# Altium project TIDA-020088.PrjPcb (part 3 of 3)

## Sheet TIDA-020088_SPDIF and Interface.SchDoc
size 431 x 279 mm; Date: Not shown in title block; ApprovedBy: Not shown in title block; CheckedBy: Not shown in title block; Author: Not shown in title block; CompanyName: Not shown in title block; Engineer: Not shown in title block; Organization: Not shown in title block; Address1: Not shown in title block; Address2: Not shown in title block; Address3: Not shown in title block; Address4: Not shown in title block; DocumentNumber: 2; Revision: Use project parameter SCH_Rev; SheetNumber: 6; SheetTotal: 7; PageSetup: Record=PageOptions¦CenterHorizontal=True¦CenterVertical=True¦PrintScale=1.00¦XCorrection=1.00¦YCorrection=1.00¦PrintKind=0¦BorderSize=5000000¦LeftOffset=0¦BottomOffset=0¦Orientation=2¦PaperLength=1000¦PaperWidth=1000¦Scale=100¦PaperSource=15¦PrintQuality=600¦MediaType=1¦DitherType=10¦PaperKind=Letter¦PrintScaleMode=1
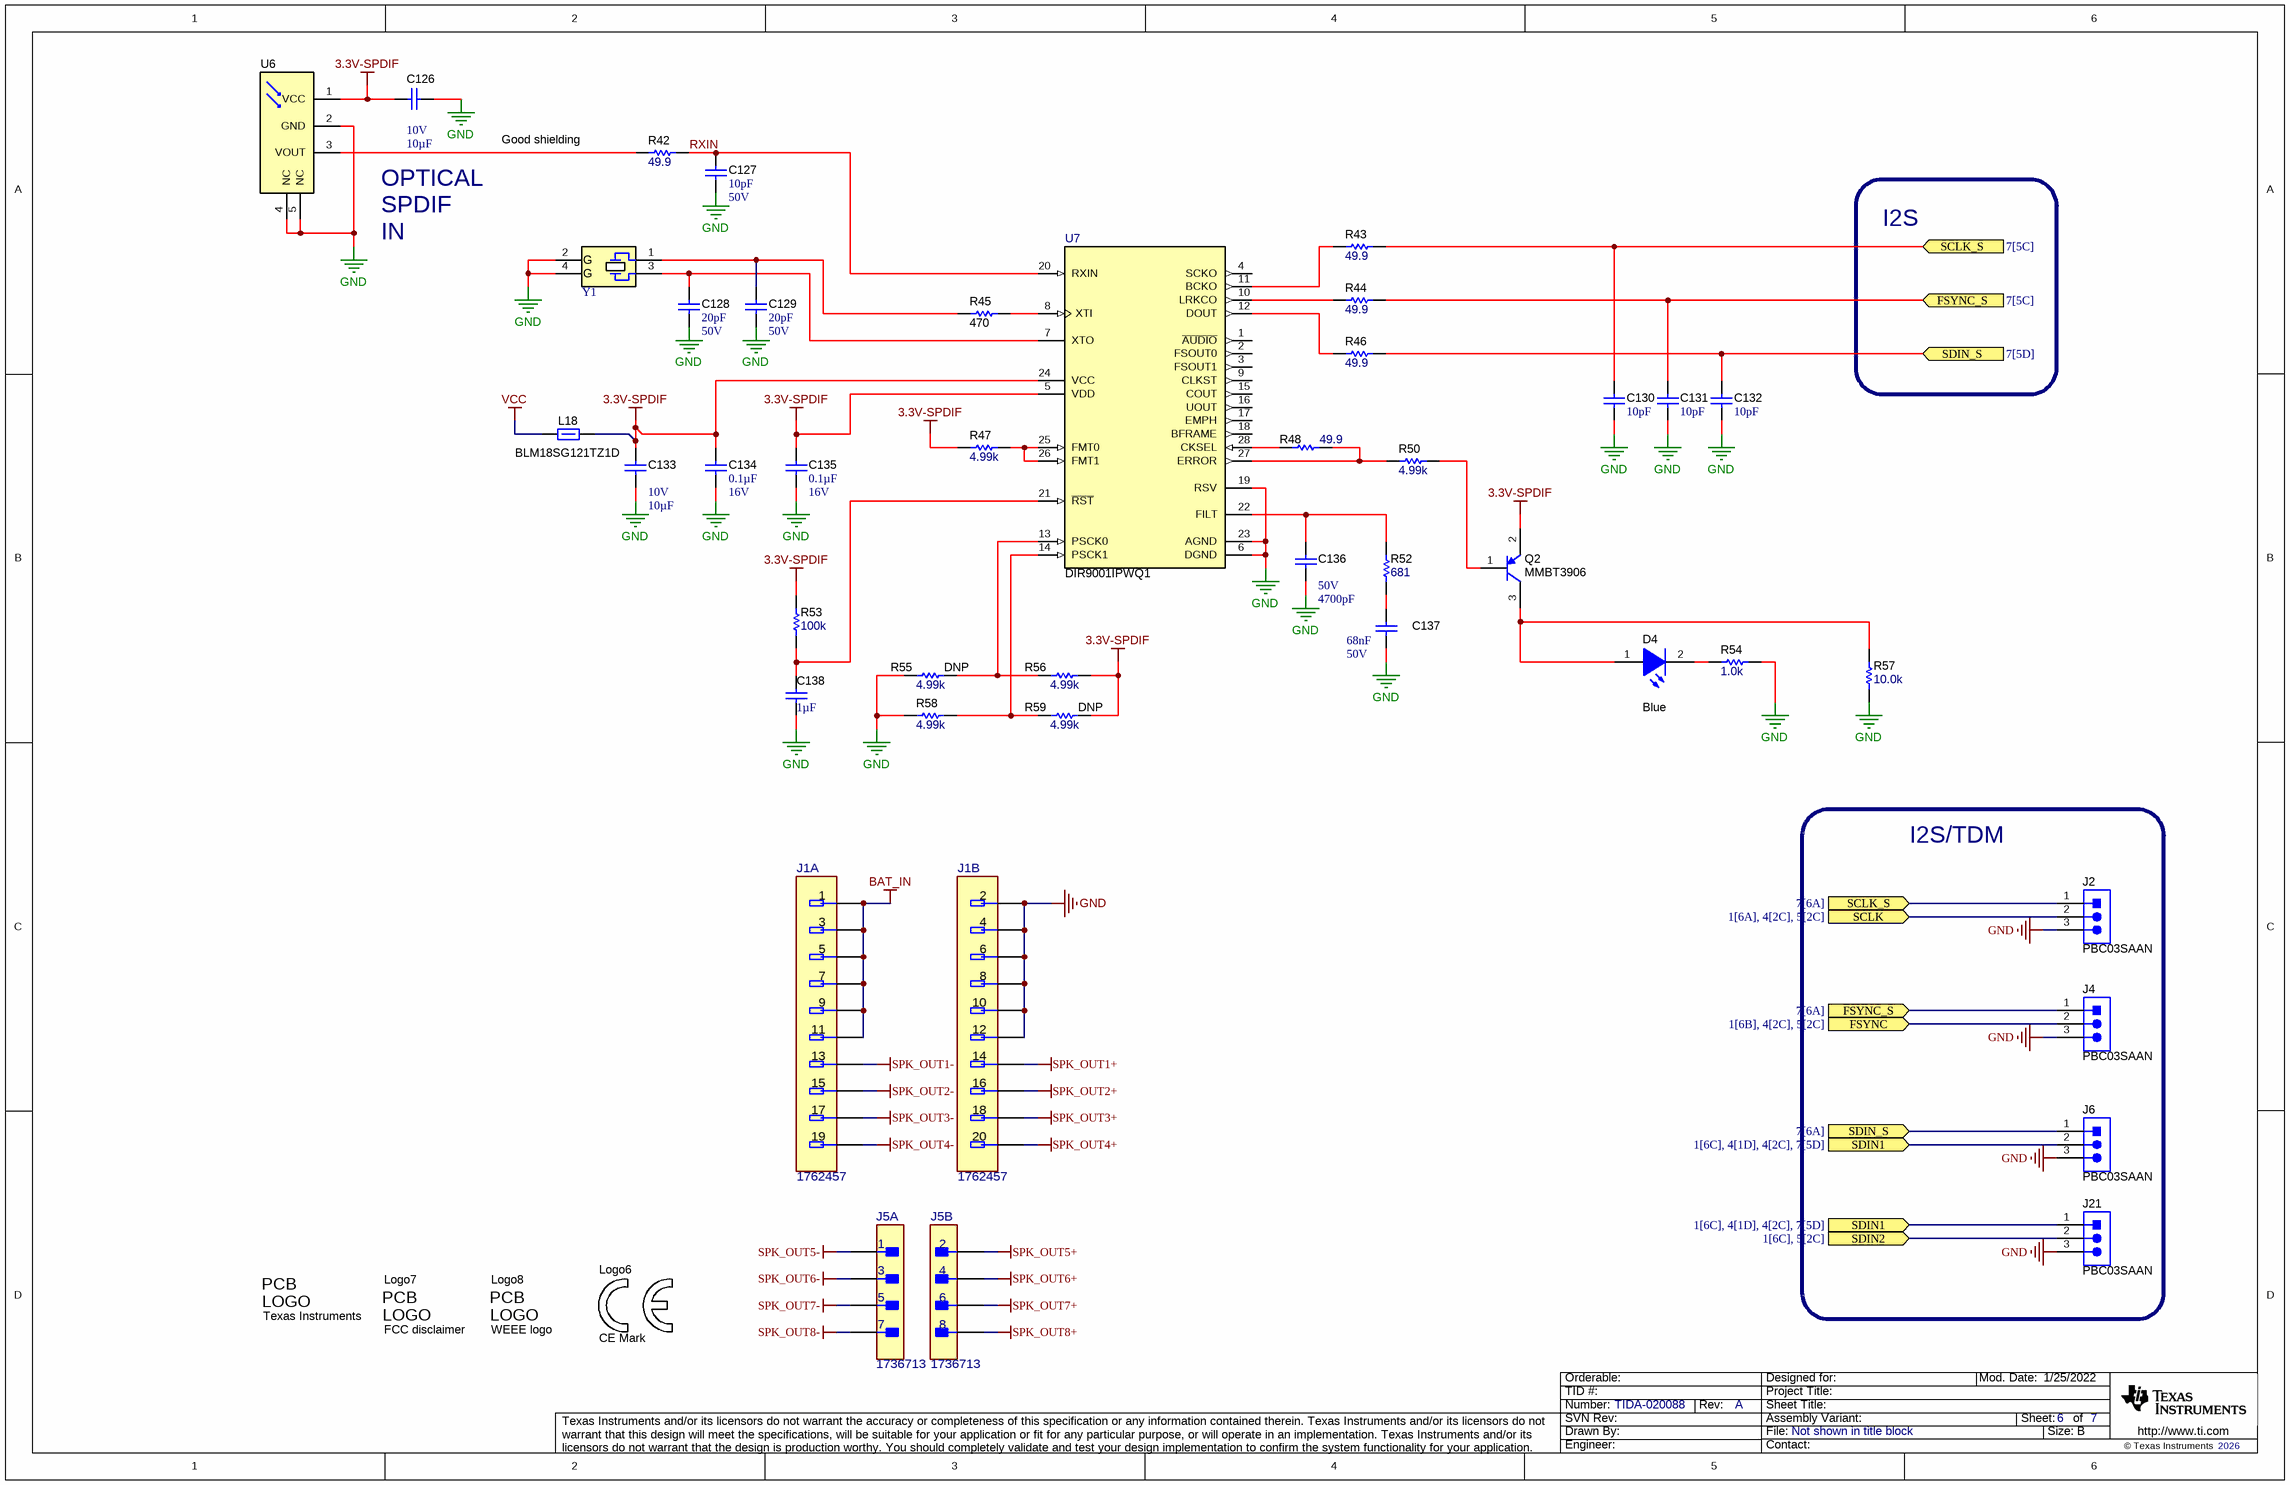
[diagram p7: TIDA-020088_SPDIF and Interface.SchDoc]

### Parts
C126  VDC_V: 10V  ValueDisplayed: 10µF  [0805_HV]  (hidden comment: C0805C106J8RACAUTO)
C127  ValueDisplayed: 10pF  VDC_V: 50V  [0402]  (hidden comment: GCM1555C1H100JA16D)
C128  ValueDisplayed: 20pF  VDC_V: 50V  [0402]  (hidden comment: GCQ1555C1H200JB01D)
C129  ValueDisplayed: 20pF  VDC_V: 50V  [0402]  (hidden comment: GCQ1555C1H200JB01D)
C130  ValueDisplayed: 10pF  [0402]  (hidden comment: GCM1555C1H100JA16D)
C131  ValueDisplayed: 10pF  [0402]  (hidden comment: GCM1555C1H100JA16D)
C132  ValueDisplayed: 10pF  [0402]  (hidden comment: GCM1555C1H100JA16D)
C133  VDC_V: 10V  ValueDisplayed: 10µF  [0805_HV]  (hidden comment: C0805C106J8RACAUTO)
C134  ValueDisplayed: 0.1µF  VDC_V: 16V  [0402]  (hidden comment: GCM155R71C104JA55D)
C135  ValueDisplayed: 0.1µF  VDC_V: 16V  [0402]  (hidden comment: GCM155R71C104JA55D)
C136  VDC_V: 50V  ValueDisplayed: 4700pF  [0402]  (hidden comment: GCM155R71H472KA37D)
C137  Cap_F: 68nF  VDC_V: 50V  [0603]  (hidden comment: CGA3E2X7R1H683K080AA)
C138  Cap_F: 1µF  [0603]  (hidden comment: GCM188R71E105KA64D)
D4  value Blue  [LED_SMLP12_BLUE]  (hidden comment: CMP-0002838-1)
J1  1762457  [FP-1762457_HDR20-MFG]  (parts A,B of 2)
J2  PBC03SAAN  [PBC03SAAN]
J4  PBC03SAAN  [PBC03SAAN]
J5  1736713  [FP-1736713_HDR8-MFG]  (parts A,B of 2)
J6  PBC03SAAN  [PBC03SAAN]
J21  PBC03SAAN  [PBC03SAAN]
L18  BLM18SG121TZ1D  [0603]
Logo5  Texas Instruments  [TI_Stacked_Overlay_Small]  (no BOM)
Logo6  CE Mark  [CE_Mark_5mm]  (no BOM)
Logo7  FCC disclaimer  [FCC_disclaimer_stacked]  (no BOM)
Logo8  WEEE logo  [WEEE_Minimum]  (no BOM)
Q2  MMBT3906  [SOT-23]
R42  ValueDisplayed: 49.9  [0402L]  (hidden comment: CMP-0026404-2)
R43  ValueDisplayed: 49.9  [0402L]  (hidden comment: CMP-0026404-2)
R44  ValueDisplayed: 49.9  [0402L]  (hidden comment: CMP-0026404-2)
R45  ValueDisplayed: 470  [0402L]  (hidden comment: CRCW0402470RJNED)
R46  ValueDisplayed: 49.9  [0402L]  (hidden comment: CMP-0026404-2)
R47  ValueDisplayed: 4.99k  [0402L]  (hidden comment: CMP-0026414-2)
R48  ValueDisplayed: 49.9  [0402L]  (hidden comment: CMP-0026404-2)
R50  ValueDisplayed: 4.99k  [0402L]  (hidden comment: CMP-0026414-2)
R52  ValueDisplayed: 681  [0402L]  (hidden comment: CMP-0026505-2)
R53  ValueDisplayed: 100k  [0402L]  (hidden comment: CMP-0025950-3)
R54  ValueDisplayed: 1.0k  [0402L]  (hidden comment: CRCW04021K00JNED)
R55  DNP  ValueDisplayed: 4.99k  [0402L]
R56  ValueDisplayed: 4.99k  [0402L]  (hidden comment: CMP-0026414-2)
R57  ValueDisplayed: 10.0k  [0402L]  (hidden comment: CMP-0025958-3)
R58  ValueDisplayed: 4.99k  [0402L]  (hidden comment: CMP-0026414-2)
R59  DNP  ValueDisplayed: 4.99k  [0402L]
U6  CMP-0004896-1  [PLR135_T10]  (value not drawn)
U7  PartNumber: DIR9001IPWQ1  [PW0028A_N]  (hidden comment: TI-DIR9001-Q1-TSSOP_PW-28)
Y1  ABM10-24.576MHZ-E20-T  [XTAL_ABM10]  (value not drawn)

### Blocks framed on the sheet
I2S/TDM: J2 J4 J6 J21

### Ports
FSYNC (in, see 1[6B], 4[2C], 5[2C]), FSYNC_S (in, see 7[5C]), FSYNC_S (in, see 7[6A]), SCLK (in, see 1[6A], 4[2C], 5[2C]), SCLK_S (in, see 7[5C]), SCLK_S (in, see 7[6A]), SDIN1 (in, see 1[6C], 4[1D], 4[2C], 7[5D]), SDIN2 (in, see 1[6C], 5[2C]), SDIN_S (in, see 7[5D]), SDIN_S (in, see 7[6A])

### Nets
3.3V-SPDIF: C126.1 C133.1 C134.2 C135.2 L18.1 Q2.2(E) R47.2 R53.2 R56.1 R59.1 U6.1(VCC) U7.5(VDD) U7.24(VCC)
BAT_IN: J1.1 J1.3 J1.5 J1.7 J1.9 J1.11
GND: C126.2 C127.2 C128.2 C129.2 C130.2 C131.2 C132.2 C133.2 C134.1 C135.1 C136.2 C137.2 C138.2 J1.2 J1.4 J1.6 J1.8 J1.10 J1.12 J2.3 J4.3 J6.3 J21.3 R54.2 R55.2 R57.1 R58.2 U6.2(GND) U6.4(NC) U6.5(NC) U7.6(DGND) U7.19(RSV) U7.23(AGND) Y1.2(GND) Y1.4(GND)
SPK_OUT1+: J1.14
SPK_OUT1-: J1.13
SPK_OUT2+: J1.16
SPK_OUT2-: J1.15
SPK_OUT3+: J1.18
SPK_OUT3-: J1.17
SPK_OUT4+: J1.20
SPK_OUT4-: J1.19
SPK_OUT5+: J5.2
SPK_OUT5-: J5.1
SPK_OUT6+: J5.4
SPK_OUT6-: J5.3
SPK_OUT7+: J5.6
SPK_OUT7-: J5.5
SPK_OUT8+: J5.8
SPK_OUT8-: J5.7
VCC: L18.2
RXIN: C127.1 R42.2 U7.20(RXIN)
NetC128_1: C128.1 U7.7(XTO) Y1.3
NetC129_1: C129.1 R45.1 Y1.1
NetC130_1: C130.1 J2.1 R43.2 ; port SCLK_S
NetC131_1: C131.1 J4.1 R44.2 ; port FSYNC_S
NetC132_1: C132.1 J6.1 R46.2 ; port SDIN_S
NetC136_1: C136.1 R52.2 U7.22(FILT)
NetC137_1: C137.1 R52.1
NetC138_1: C138.1 R53.1 U7.21(~{RST})
NetD4_1: D4.1(A) Q2.3(C) R57.2
NetD4_2: D4.2(K) R54.1
NetJ2_2: J2.2 ; port SCLK
NetJ4_2: J4.2 ; port FSYNC
NetJ6_2: J6.2 J21.1 ; port SDIN1
NetJ19_2: J21.2 ; port SDIN2
NetQ2_1: Q2.1(B) R50.1
NetR42_1: R42.1 U6.3(VOUT)
NetR43_1: R43.1 U7.11(BCKO)
NetR44_1: R44.1 U7.10(LRKCO)
NetR45_2: R45.2 U7.8(XTI)
NetR46_1: R46.1 U7.12(DOUT)
NetR47_1: R47.1 U7.25(FMT0) U7.26(FMT1)
NetR48_1: R48.1 U7.28(CKSEL)
NetR48_2: R48.2 R50.2 U7.27(ERROR)
NetR55_1: R55.1 R56.2 U7.13(PSCK0)
NetR58_1: R58.1 R59.2 U7.14(PSCK1)

Not connected (* = marked no-connect by the designer): U7 1(~{AUDIO}) 2(FSOUT0) 3(FSOUT1) 4(SCKO) 9(CLKST) 15(COUT) 16(UOUT) 17(EMPH) 18(BFRAME)

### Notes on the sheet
- Good shielding
- OPTICAL
- SPDIF
- I2S
- IN

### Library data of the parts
C126 C133 = CMP-0081061-1: CAP, CERM, 10 µF, 10 V,+/- 5%, X7R, AEC-Q200 Grade 1, 0805; Manufacturer: Kemet; TaMin_C: -55°C; Polarized: N; SizeAreaWB_mm2: 6.75; U/M: EA; Value: 10uF; TaMax_C: 125°C; SizeZ_mm: 1.45; SizeX_mm: 2; SizeY_mm: 1.25; Cap_Case: 0805; SizeArea_mm2: 2.5; AEC Qualified: Y; AEC Grade: 1; AEC Category: Q200
C127 = CMP-0860290-1: CAP, CERM, 10 pF, 50 V,+/- 5%, C0G/NP0, AEC-Q200 Grade 1, 0402; Manufacturer: MuRata; Polarized: N; Value: 10pF; U/M: EA; TaMin_C: -55°C; TaMax_C: 125°C; SizeAreaWB_mm2: 3; SizeZ_mm: 0.6; SizeX_mm: 1; SizeY_mm: 0.5; AEC Qualified: Y; AEC Category: Q200
C128 C129 = CMP-0085255-1: CAP, CERM, 20 pF, 50 V,+/- 5%, C0G/NP0, AEC-Q200 Grade 1, 0402; Manufacturer: MuRata; SizeX_mm: 1; Value: 20pF; SizeAreaWB_mm2: 3; TaMin_C: -55°C; AEC Category: Q200; Polarized: N; SizeY_mm: 0.5; U/M: EA; AEC Qualified: Y; TaMax_C: 125°C; SizeZ_mm: 0.6
C130-C132 = CMP-0860290-1: CAP, CERM, 10 pF, 50 V,+/- 5%, C0G/NP0, AEC-Q200 Grade 1, 0402; Manufacturer: MuRata; Polarized: N; Value: 10pF; U/M: EA; VDC_V: 50V; TaMin_C: -55°C; TaMax_C: 125°C; SizeAreaWB_mm2: 3; SizeZ_mm: 0.6; SizeX_mm: 1; SizeY_mm: 0.5; AEC Qualified: Y; AEC Category: Q200
C134 C135 = CMP-0080702-1: CAP, CERM, 0.1 µF, 16 V,+/- 5%, X7R, AEC-Q200 Grade 1, 0402; Manufacturer: MuRata; Polarized: N; Value: 0.1uF; U/M: EA; Cap_F: 100nF; TaMin_C: -55°C; TaMax_C: 125°C; SizeAreaWB_mm2: 3; SizeZ_mm: 0.6; SizeX_mm: 1; SizeY_mm: 0.5; AEC Qualified: Y; AEC Category: Q200
C136 = CMP-0006361-2: CAP, CERM, 4700 pF, 50 V, +/- 10%, X7R, AEC-Q200 Grade 1, 0402; Manufacturer: MuRata; TaMin_C: -55°C; Polarized: N; SizeAreaWB_mm2: 3; Value1: Unknown; U/M: EA; Value: 4700pF; TaMax_C: 125°C; SizeZ_mm: 0.6; SizeX_mm: 1; SizeY_mm: 0.5; AEC Qualified: Y; Cap_F: 4.7nF; AEC Category: Q200
C137 = CMP-0007080-5: CAP, CERM, 0.068 uF, 50 V, +/- 10%, X7R, AEC-Q200 Grade 1, 0603; Manufacturer: TDK; TaMin_C: -55°C; ESR_ohm: 35.979m; Polarized: N; SizeAreaWB_mm2: 4.68; Value1: 0.035979 ohm; U/M: EA; TaMax_C: 125°C; SizeZ_mm: 1; SizeX_mm: 1.6; SizeY_mm: 0.8; SizeArea_mm2: 1.28; AEC Qualified: Y; IRMS_A: 886.483mA; AEC Category: Q200
C138 = CMP-0007139-4: CAP, CERM, 1 uF, 25 V, +/- 10%, X7R, AEC-Q200 Grade 1, 0603; Manufacturer: MuRata; Value: 1uF; SizeZ_mm: 1; AEC Qualified: Y; VDC_V: 25V; TaMin_C: -55°C; Polarized: N; SizeAreaWB_mm2: 4.68; Value1: Unknown; U/M: EA; TaMax_C: 125°C; SizeX_mm: 1.6; SizeY_mm: 0.8; SizeArea_mm2: 1.28; AEC Category: Q200
D4 = CMP-0002838-1: LED, Blue, SMD; Manufacturer: Rohm; PartNumber: SMLP12BC7TT86; Type: InGaN; Vf_V: 2.9V; Io_A: 5mA; Tjmax_C: 85°C; Value1: W; U/M: EA
J1 = CMP-0087217-1: TERM BLOCK HDR 20POS 5.08MM; Manufacturer: Phoenix Contact; Current_A: 10A; ContactFinish: Tin; Row_Count: 2; Voltage_V: 320V
J2 J4 J6 J21 = CMP-0002334-1: Header, 100mil, 3x1, Gold, TH; Manufacturer: Sullins Connector Solutions; CNHeader: TRUE; Green_Lifecycle: Not Set; Green_REACh: Incomplete; CT: FALSE
J5 = CMP-0093062-1: Manufacturer: Phoenix Contact; TaMax_C: +100°C; Voltage_V: 320V; TaMin_C: -40°C; Row_Count: 2; Conn Orientation: Right Angle; ContactFinish: Tin,Nickel; Current_A: 10A; SizeZ_mm: 28.7mm; Conn Gender: Male; Is Female: no; DUT-Pitch_mm: 5.08mm
L18 = CMP-0084877-1: Inductor, Ferrite Bead, Ferrite, 3 A, 120 ohm, AEC-Q200 Grade 1, SMD; Manufacturer: MuRata; SizeAreaWB_mm2: 4.68; DCR_ohm: 120; Value1: 120 ohm; Imax_A: 3A; SizeZ_mm: 1; SizeX_mm: 1.6; SizeY_mm: 0.8; SizeArea_mm2: 1.28; AEC Qualified: Y; AEC Category: Q200
Logo5 = CMP-0074838-1: Texas Instrument Corporate Signature; SymbolCreator: a0412235; Lib Reference: TI_Logo; Library Reference: Logo
Logo6 = CMP-0074844-1: SymbolCreator: a0412235
Logo7 = CMP-0074847-1: FCC_disclaimer; Library Reference: Logo
Logo8 = CMP-0074769-1
Q2 = CMP-0000325-2: Transistor, PNP, 40 V, 0.2 A, SOT-23; Manufacturer: Fairchild Semiconductor; CompType: BJT; PNP: 1; NPN: 0; Vceo_V: 40V; Vcesat1_V: 2.5dV; Value: 40 V; IcRated_A: 2dA; Value1: 0.2 A; HfeMax: 300; TaMin_C: -55°C; TaMax_C: 150°C; U/M: EA; SizeX_mm: 2.5; SizeY_mm: 3; SizeZ_mm: 1.1; SizeArea_mm2: 7.5; AEC Category: Q101; SizeAreaWB_mm2: 14
R42-R44 R46 R48 = CMP-0026404-2: RES, 49.9, 1%, 0.063 W, AEC-Q200 Grade 0, 0402; PartNumber: CRCW040249R9FKED; Manufacturer: Vishay-Dale; Value: 49.9; Value_Code: 49R9; Power_W: 63mW; Value2: 0.063W; VDC_V: 50V; TempCo: 100 ppm/C; EIA_Code: E96; SizeX_mm: 1; SizeY_mm: 0.5; SizeZ_mm: 0.6; AEC Qualified: Y; AEC Category: Q200; AEC Grade: 0
R45 = CMP-0026934-3: RES, 470, 5%, 0.063 W, AEC-Q200 Grade 0, 0402; Manufacturer: Vishay-Dale; Power_W: 63mW; TempCo: 200 ppm/C; Value_Code: 470R; Value: 470; EIA_Code: E24; SizeX_mm: 1; SizeY_mm: 0.5; SizeZ_mm: 0.6; Value2: 0.063W; AEC Qualified: Y; VDC_V: 50V; AEC Category: Q200; AEC Grade: 0
R47 R50 R56 R58 = CMP-0026414-2: RES, 4.99 k, 1%, 0.063 W, AEC-Q200 Grade 0, 0402; PartNumber: CRCW04024K99FKED; Manufacturer: Vishay-Dale; Value: 4.99k; Value_Code: 4k99; Power_W: 63mW; Value2: 0.063W; VDC_V: 50V; TempCo: 100 ppm/C; EIA_Code: E96; SizeX_mm: 1; SizeY_mm: 0.5; SizeZ_mm: 0.6; AEC Qualified: Y; AEC Category: Q200; AEC Grade: 0
R52 = CMP-0026505-2: RES, 681, 1%, 0.063 W, AEC-Q200 Grade 0, 0402; PartNumber: CRCW0402681RFKED; Manufacturer: Vishay-Dale; Value: 681; Value_Code: 681R; Power_W: 63mW; Value2: 0.063W; VDC_V: 50V; TempCo: 100 ppm/C; EIA_Code: E96; SizeX_mm: 1; SizeY_mm: 0.5; SizeZ_mm: 0.6; AEC Qualified: Y; AEC Category: Q200; AEC Grade: 0
R53 = CMP-0025950-3: RES, 100 k, 1%, 0.063 W, AEC-Q200 Grade 0, 0402; PartNumber: CRCW0402100KFKED; Manufacturer: Vishay-Dale; Value: 100k; Power_W: 63mW; Value2: 0.063W; VDC_V: 50V; TempCo: 100 ppm/C; EIA_Code: E96; SizeX_mm: 1; SizeY_mm: 0.5; SizeZ_mm: 0.6; AEC Qualified: Y; AEC Category: Q200; AEC Grade: 0
R54 = CMP-0026852-3: RES, 1.0 k, 5%, 0.063 W, AEC-Q200 Grade 0, 0402; Manufacturer: Vishay-Dale; Power_W: 63mW; TempCo: 200 ppm/C; Value_Code: 1k00; Value: 1.0k; EIA_Code: E24; Res_ohm: 1k; SizeX_mm: 1; SizeY_mm: 0.5; SizeZ_mm: 0.6; Value2: 0.063W; CompType: Resistor; AEC Qualified: Y; VDC_V: 50V; AEC Category: Q200; AEC Grade: 0
R55 R59 = CMP-0026414-2: RES, 4.99 k, 1%, 0.063 W, AEC-Q200 Grade 0, 0402; PartNumber: CRCW04024K99FKED; Manufacturer: Vishay-Dale; CompType: Resistor; Value: 4.99k; Value_Code: 4k99; Power_W: 63mW; Value2: 0.063W; VDC_V: 50V; TempCo: 100 ppm/C; EIA_Code: E96; SizeX_mm: 1; SizeY_mm: 0.5; SizeZ_mm: 0.6; AEC Qualified: Y; AEC Category: Q200; AEC Grade: 0
R57 = CMP-0025958-3: RES, 10.0 k, 1%, 0.063 W, AEC-Q200 Grade 0, 0402; PartNumber: CRCW040210K0FKED; Manufacturer: Vishay-Dale; Value: 10.0k; Res_ohm: 10k; Value_Code: 10k0; Power_W: 63mW; Value2: 0.063W; VDC_V: 50V; TempCo: 100 ppm/C; EIA_Code: E96; SizeX_mm: 1; SizeY_mm: 0.5; SizeZ_mm: 0.6; AEC Qualified: Y; AEC Category: Q200; AEC Grade: 0
U6 = CMP-0004896-1: Photolink- Fiber Optic Receiver, TH; PartNumber: PLR135/T10; Manufacturer: Everlight
U7 = CMP-0028713-1: Automotive Catalog 96-kHz 24-Bit Digital Audio Interface Receiver, 50 ps Jitter, 3.3V, -40 to 85 degC, 28-Pin TSSOP (PW), Green (RoHS & no Sb/Br); Manufacturer: Texas Instruments; SubFamily: Digital Audio Receiver; Jitter(ps): 50; Sampling Rate(Max)(kHz): 108; Supply Voltage(s)(V): 3.3
Y1 = CMP-0004590-1: Crystal, 24.576 MHz, 10pF, SMD; Manufacturer: Abracon Corporation; TaMin_C: -20°C; Frequency Stability: +/-20ppm; U/M: EA; TaMax_C: 70°C

## Sheet Hardware.SchDoc
size 431 x 279 mm; Date: Not shown in title block; ApprovedBy: Not shown in title block; CheckedBy: Not shown in title block; Author: Not shown in title block; CompanyName: Not shown in title block; Engineer: Not shown in title block; Organization: Not shown in title block; Address1: Not shown in title block; Address2: Not shown in title block; Address3: Not shown in title block; Address4: Not shown in title block; DocumentNumber: 3; Revision: Use project parameter SCH_Rev; SheetNumber: 8; SheetTotal: 8; PageSetup: Record=PageOptions¦CenterHorizontal=True¦CenterVertical=True¦PrintScale=1.00¦XCorrection=1.00¦YCorrection=1.00¦PrintKind=0¦BorderSize=5000000¦LeftOffset=0¦BottomOffset=0¦Orientation=2¦PaperLength=1000¦PaperWidth=1000¦Scale=100¦PaperSource=15¦PrintQuality=600¦MediaType=1¦DitherType=10¦PaperKind=Letter¦PrintScaleMode=1
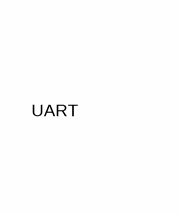
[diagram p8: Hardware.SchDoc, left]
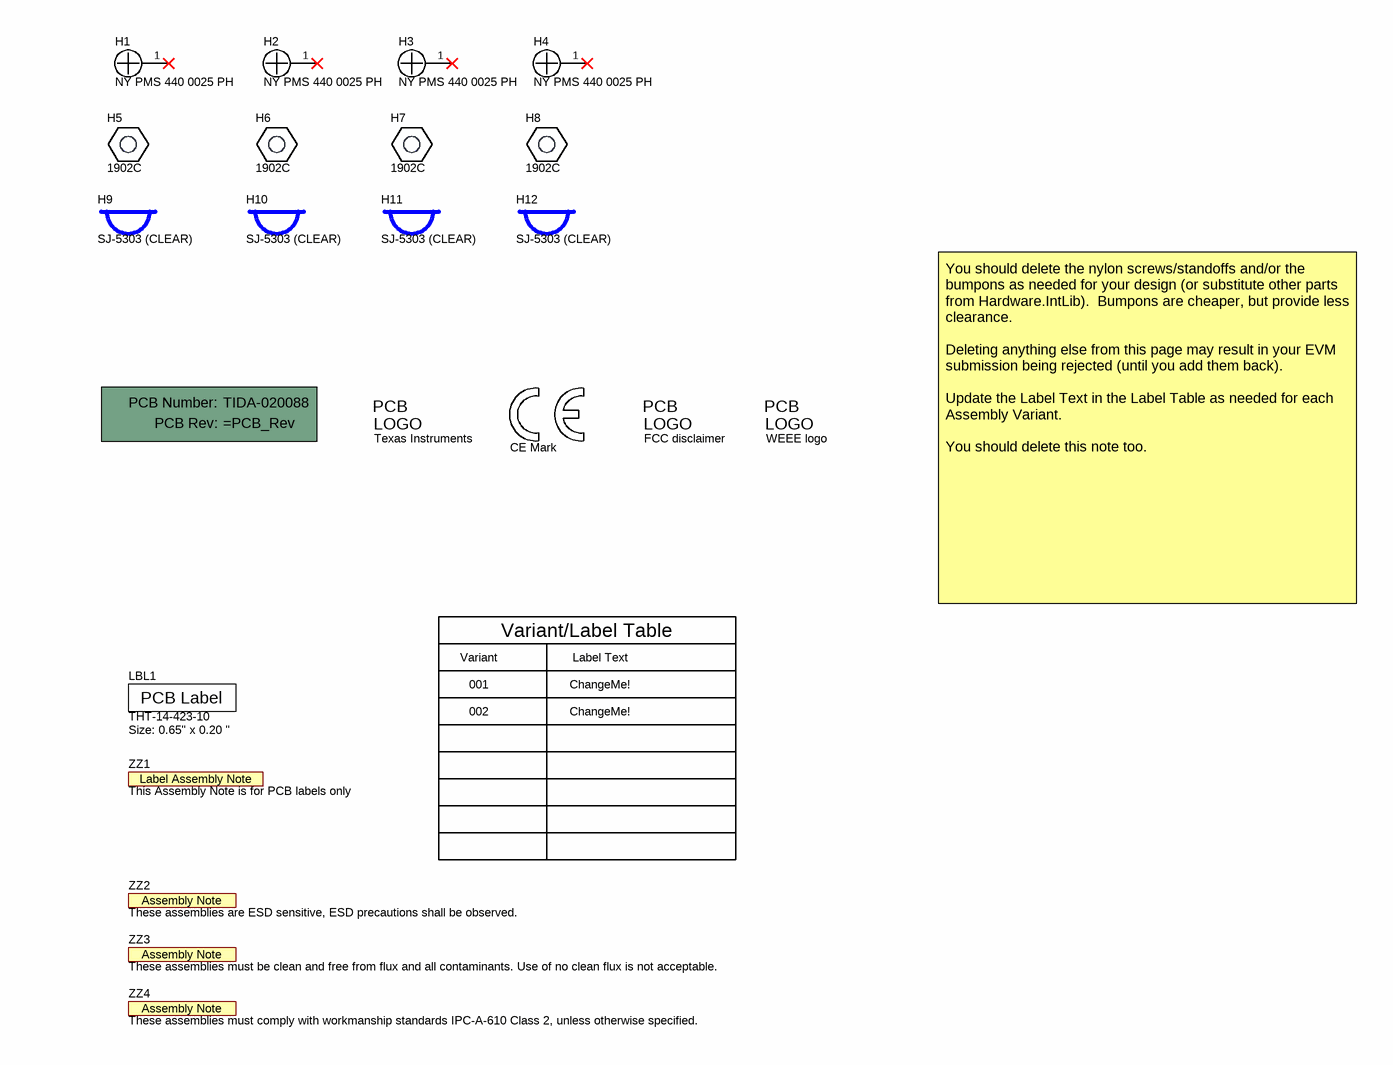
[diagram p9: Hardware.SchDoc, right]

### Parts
!PCB1  Printed Circuit Board  (value not drawn)  (mechanical)
H1  NY PMS 440 0025 PH  [NY PMS 440 0025 PH]
H2  NY PMS 440 0025 PH  [NY PMS 440 0025 PH]
H3  NY PMS 440 0025 PH  [NY PMS 440 0025 PH]
H4  NY PMS 440 0025 PH  [NY PMS 440 0025 PH]
H5  1902C  [Keystone_1902C]
H6  1902C  [Keystone_1902C]
H7  1902C  [Keystone_1902C]
H8  1902C  [Keystone_1902C]
H9  SJ-5303 (CLEAR)  [Bumpon_SJ5003Transparent]
H10  SJ-5303 (CLEAR)  [Bumpon_SJ5003Transparent]
H11  SJ-5303 (CLEAR)  [Bumpon_SJ5003Transparent]
H12  SJ-5303 (CLEAR)  [Bumpon_SJ5003Transparent]
LBL1  THT-14-423-10  Note: Size: 0.65" x 0.20 "  [Label_650x200]
Logo1  CE Mark  [CE_Mark_5mm]  (no BOM)
Logo2  Texas Instruments  [TI_Stacked_Overlay_Small]  (no BOM)
Logo3  FCC disclaimer  [FCC_disclaimer]  (no BOM)
Logo4  WEEE logo  [WEEE_Minimum]  (no BOM)
ZZ1  This Assembly Note is for PCB labels only  [AssemblyNoteLabel]  (no BOM)
ZZ2  These assemblies are ESD sensitive, ESD precautions shall be observed.  [AssemblyNote]  (no BOM)
ZZ3  These assemblies must be clean and free from flux and all contaminants. Use of no clean flux is not acceptable.  [AssemblyNote]  (no BOM)
ZZ4  These assemblies must comply with workmanship standards IPC-A-610 Class 2, unless otherwise specified.  [AssemblyNote]  (no BOM)

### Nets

Not connected (* = marked no-connect by the designer): H1 1*; H2 1*; H3 1*; H4 1*

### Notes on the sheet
- UART
- Variant
- Variant/Label Table
- Label Text
- You should delete the nylon screws/standoffs and/or the bumpons as needed for your design (or substitute other parts from Hardware.IntLib).  Bumpons are cheaper, but provide less clearance.
  Deleting anything else from this page may result in your EVM submission being rejected (until you add them back).
  Update the Label Text in the Label Table as needed for each Assembly Variant.
  You should delete this note too.
- 001
- 002
- ChangeMe!

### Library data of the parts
!PCB1 = CMP-0003618-2: Manufacturer: Any; PartNumber: TIDA-020088
H1-H4 = CMP-0003617-1: Machine Screw, Round, #4-40 x 1/4, Nylon, Philips panhead; Manufacturer: B&F Fastener Supply; CompType: Hardware
H5-H8 = CMP-0003610-1: Standoff, Hex, 0.5"L #4-40 Nylon; Manufacturer: Keystone; CompType: Hardware
H9-H12 = CMP-0003620-1: Bumpon, Hemisphere, 0.44 X 0.20, Clear; Manufacturer: 3M
LBL1 = CMP-0003625-1: Thermal Transfer Printable Labels, 0.650" W x 0.200" H - 10,000 per roll; Manufacturer: Brady; CompType: Label
Logo1 = CMP-0074844-1: SymbolCreator: a0412235
Logo2 = CMP-0074838-1: as Logo5 on sheet TIDA-020088_SPDIF and Interface
Logo3 = CMP-0074847-1: FCC_disclaimer; Library Reference: Logo
Logo4 = CMP-0074769-1
ZZ1 = CMP-0003616-3
ZZ2 = CMP-0077236-1
ZZ3 = CMP-0077237-1
ZZ4 = CMP-0077238-1

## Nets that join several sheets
3V3: TIDA-020088_Vbat_Input (L17.2 TP72.1), TIDA-020088_MCU-MSPM0G3519SPZR (13 pins)
BAT_IN: TIDA-020088_Vbat_Input (7 pins), TIDA-020088_SPDIF and Interface (6 pins)
BIAS: TIDA-020088_Vbat_Input (16 pins), TIDA-020088_LM5125 (15 pins), TIDA-020088_TAS6684_1 (L1.1), TIDA-020088_TAS6684_2 (L6.1)
EN2: TIDA-020088_LM5125 (R97.2 R101.1 U8.30), TIDA-020088_MCU-MSPM0G3519SPZR (R145.2)
GND: TIDA-020088_Interface (34 pins), TIDA-020088_Vbat_Input (28 pins), TIDA-020088_LM5125 (60 pins), TIDA-020088_TAS6684_1 (59 pins), TIDA-020088_TAS6684_2 (59 pins), TIDA-020088_MCU-MSPM0G3519SPZR (36 pins), TIDA-020088_SPDIF and Interface (35 pins)
Input_voltage_sense: TIDA-020088_LM5125 (R62.2 R63.1), TIDA-020088_MCU-MSPM0G3519SPZR (R66.1)
MODE: TIDA-020088_LM5125 (R114.2 R115.1 U8.29), TIDA-020088_MCU-MSPM0G3519SPZR (R144.2)
PVDD_1: TIDA-020088_LM5125 (8 pins), TIDA-020088_TAS6684_1 (20 pins)
PVDD_2: TIDA-020088_LM5125 (8 pins), TIDA-020088_TAS6684_2 (20 pins)
PVDD_voltage_sense: TIDA-020088_LM5125 (R49.2 R51.1), TIDA-020088_MCU-MSPM0G3519SPZR (R67.1)
SPK_OUT1+: TIDA-020088_TAS6684_1 (C23.1 C27.1 R2.2 TP8.1), TIDA-020088_SPDIF and Interface (J1.14)
SPK_OUT1-: TIDA-020088_TAS6684_1 (C24.1 C28.1 R4.2 TP10.1), TIDA-020088_SPDIF and Interface (J1.13)
SPK_OUT2+: TIDA-020088_TAS6684_1 (C31.1 C35.1 R8.2 TP14.1), TIDA-020088_SPDIF and Interface (J1.16)
SPK_OUT2-: TIDA-020088_TAS6684_1 (C32.1 C36.1 R10.2 TP16.1), TIDA-020088_SPDIF and Interface (J1.15)
SPK_OUT3+: TIDA-020088_TAS6684_1 (C39.1 C43.1 R12.2 TP20.1), TIDA-020088_SPDIF and Interface (J1.18)
SPK_OUT3-: TIDA-020088_TAS6684_1 (C40.1 C44.1 R13.2 TP22.1), TIDA-020088_SPDIF and Interface (J1.17)
SPK_OUT4+: TIDA-020088_TAS6684_1 (C47.1 C51.1 R14.2 TP26.1), TIDA-020088_SPDIF and Interface (J1.20)
SPK_OUT4-: TIDA-020088_TAS6684_1 (C48.1 C52.1 R17.2 TP28.1), TIDA-020088_SPDIF and Interface (J1.19)
SPK_OUT5+: TIDA-020088_TAS6684_2 (C75.1 C79.1 R21.2 TP37.1), TIDA-020088_SPDIF and Interface (J5.2)
SPK_OUT5-: TIDA-020088_TAS6684_2 (C76.1 C80.1 R23.2 TP39.1), TIDA-020088_SPDIF and Interface (J5.1)
SPK_OUT6+: TIDA-020088_TAS6684_2 (C83.1 C87.1 R27.2 TP43.1), TIDA-020088_SPDIF and Interface (J5.4)
SPK_OUT6-: TIDA-020088_TAS6684_2 (C84.1 C88.1 R28.2 TP45.1), TIDA-020088_SPDIF and Interface (J5.3)
SPK_OUT7+: TIDA-020088_TAS6684_2 (C91.1 C95.1 R30.2 TP49.1), TIDA-020088_SPDIF and Interface (J5.6)
SPK_OUT7-: TIDA-020088_TAS6684_2 (C92.1 C96.1 R31.2 TP51.1), TIDA-020088_SPDIF and Interface (J5.5)
SPK_OUT8+: TIDA-020088_TAS6684_2 (C99.1 C103.1 R32.2 TP55.1), TIDA-020088_SPDIF and Interface (J5.8)
SPK_OUT8-: TIDA-020088_TAS6684_2 (C100.1 C104.1 R33.2 TP57.1), TIDA-020088_SPDIF and Interface (J5.7)
UVLO/EN: TIDA-020088_LM5125 (C181.1 R64.1 R94.2 U8.19), TIDA-020088_MCU-MSPM0G3519SPZR (R146.2)
VCC: TIDA-020088_Interface (16 pins), TIDA-020088_Vbat_Input (5 pins), TIDA-020088_LM5125 (5 pins), TIDA-020088_TAS6684_1 (11 pins), TIDA-020088_TAS6684_2 (9 pins), TIDA-020088_SPDIF and Interface (L18.2)
VCC_LDO_5V: TIDA-020088_Vbat_Input (C114.1 U15.4), TIDA-020088_MCU-MSPM0G3519SPZR (C154.2 C172.1 U16.3)
NetJ2_2: TIDA-020088_Interface (J3.2), TIDA-020088_TAS6684_1 (U1.5), TIDA-020088_TAS6684_2 (U2.5), TIDA-020088_SPDIF and Interface (J2.2)
NetJ4_2: TIDA-020088_Interface (J17.2), TIDA-020088_TAS6684_1 (U1.6), TIDA-020088_TAS6684_2 (U2.6), TIDA-020088_SPDIF and Interface (J4.2)
NetJ6_2: TIDA-020088_Interface (J18.2), TIDA-020088_TAS6684_1 (J22.2 U1.7), TIDA-020088_SPDIF and Interface (J6.2 J21.1)
NetJ11_2: TIDA-020088_Interface (R157.2), TIDA-020088_TAS6684_1 (R15.1 U1.13), TIDA-020088_TAS6684_2 (U2.13), TIDA-020088_MCU-MSPM0G3519SPZR (J11.2 R123.2)
NetJ11_3: TIDA-020088_Interface (R158.2), TIDA-020088_TAS6684_1 (R16.1 U1.12), TIDA-020088_TAS6684_2 (U2.12), TIDA-020088_MCU-MSPM0G3519SPZR (J11.3 R128.2)
NetJ19_2: TIDA-020088_Interface (J19.2), TIDA-020088_TAS6684_2 (J20.2 U2.7), TIDA-020088_SPDIF and Interface (J21.2)
NetR1_2: TIDA-020088_TAS6684_1 (R1.2 R61.1), TIDA-020088_MCU-MSPM0G3519SPZR (R125.2)
NetR3_1: TIDA-020088_TAS6684_1 (R3.1 R60.1), TIDA-020088_MCU-MSPM0G3519SPZR (R130.2)
NetR5_1: TIDA-020088_LM5125 (R102.1 R113.1), TIDA-020088_TAS6684_1 (R5.1 U1.62), TIDA-020088_MCU-MSPM0G3519SPZR (R138.2)
NetR6_1: TIDA-020088_LM5125 (R98.1), TIDA-020088_TAS6684_1 (R6.1 R9.1 U1.10), TIDA-020088_MCU-MSPM0G3519SPZR (R137.2)
NetR9_2: TIDA-020088_TAS6684_1 (R9.2), TIDA-020088_TAS6684_2 (R25.1 U2.10), TIDA-020088_MCU-MSPM0G3519SPZR (R140.2)
NetR11_1: TIDA-020088_TAS6684_2 (R11.1 R22.1), TIDA-020088_MCU-MSPM0G3519SPZR (R133.2)
NetR20_2: TIDA-020088_TAS6684_2 (R20.2 R29.1), TIDA-020088_MCU-MSPM0G3519SPZR (R132.2)
NetR24_1: TIDA-020088_LM5125 (R109.2 R113.2), TIDA-020088_TAS6684_2 (R24.1 U2.62), TIDA-020088_MCU-MSPM0G3519SPZR (R141.2)
NetR142_2: TIDA-020088_TAS6684_1 (R172.1 U1.8), TIDA-020088_MCU-MSPM0G3519SPZR (R142.2)
NetR143_2: TIDA-020088_TAS6684_1 (R172.2 TP82.1), TIDA-020088_TAS6684_2 (U2.8), TIDA-020088_MCU-MSPM0G3519SPZR (R143.2)
PA8_UART1-TX: TIDA-020088_Interface (R166.2), TIDA-020088_MCU-MSPM0G3519SPZR (J13.2 U10.56)
PA9_UART1-RX: TIDA-020088_Interface (R167.2), TIDA-020088_MCU-MSPM0G3519SPZR (J13.3 U10.57)

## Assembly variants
001: all parts fitted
